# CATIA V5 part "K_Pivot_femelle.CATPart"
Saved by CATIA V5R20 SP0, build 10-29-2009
Part number: pivot_femelle
Bounding box of the stored display mesh (mm): x -21.5 to 18.5, y -35 to 35, z -16 to 16
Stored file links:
  G:\Khaled_CFAO_2011\ST2M\ST2M_GR1\lpierredon\Khaled\CAD_thinkMOTION\K_Pivot_femelle.CATPart
  F:\CATIA LIO\stepper.CATProduct
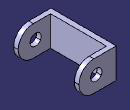
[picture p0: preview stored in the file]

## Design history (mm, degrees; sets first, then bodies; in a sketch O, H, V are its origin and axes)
Set1
  Plane1: linked copy from another document
  Point1: linked copy from another document
  Plane2: linked copy from another document
  Line1: linked copy from another document
Body1 (main body)
  Sketch1 on Plane1, origin (0, 35, 0), H (-1, 0, 0), V (0, 0, 1)
    line L1 (21.5, 16) -> (-18.5, 16)
    line L2 (-18.5, 16) -> (-18.5, -16)
    line L3 (-18.5, -16) -> (21.5, -16)
    line L4 (21.5, -16) -> (21.5, 16)
    reference projected point E1 (0, 0) from Point1
    distance L4 L2 = 40
    distance L4 E1 = 21.5
    horizontal: L1 H, L3 H
    vertical: L2 V, L4 V
    symmetry: L1 L3 H
  Pad1: profile Sketch1, direction (0, 1, 0), up to Plane2
  Sketch2 on Plane1, origin (0, 35, 0), H (1, 0, 0), V (0, 0, -1)
    point P1 (0, 0)
    reference projected point E1 (0, 0) from Point1
    coincidence: E1 P1
  Hole1: placed by Sketch2, at (0, 35, 0) direction (0, -1, 0), diameter 12, depth 70
  Fillet1: radius 16, on edge [face of Pad1 from Sketch1.L1 | face of Pad1 from Sketch1.L2]; edge [face of Pad1 from Sketch1.L2 | face of Pad1 from Sketch1.L3]
  Sketch3 on xy-plane, origin (0, 0, 0), H (1, 0, 0), V (0, 1, 0)
    line L1 (-16, 30) -> (27, 30)
    line L2 (27, 30) -> (27, -30)
    line L3 (27, -30) -> (-16, -30)
    line L4 (-16, -30) -> (-16, 30)
    reference projected line E1 (0, -35) -> (0, 35) from Line1
    distance L4 E1 = 16
    length L2 = 60
    horizontal: L1 H, L3 H
    vertical: L2 V, L4 V
    symmetry: L1 L3 H
  Pocket1: profile Sketch3, direction (0, 0, -1), length 20, mirrored extent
